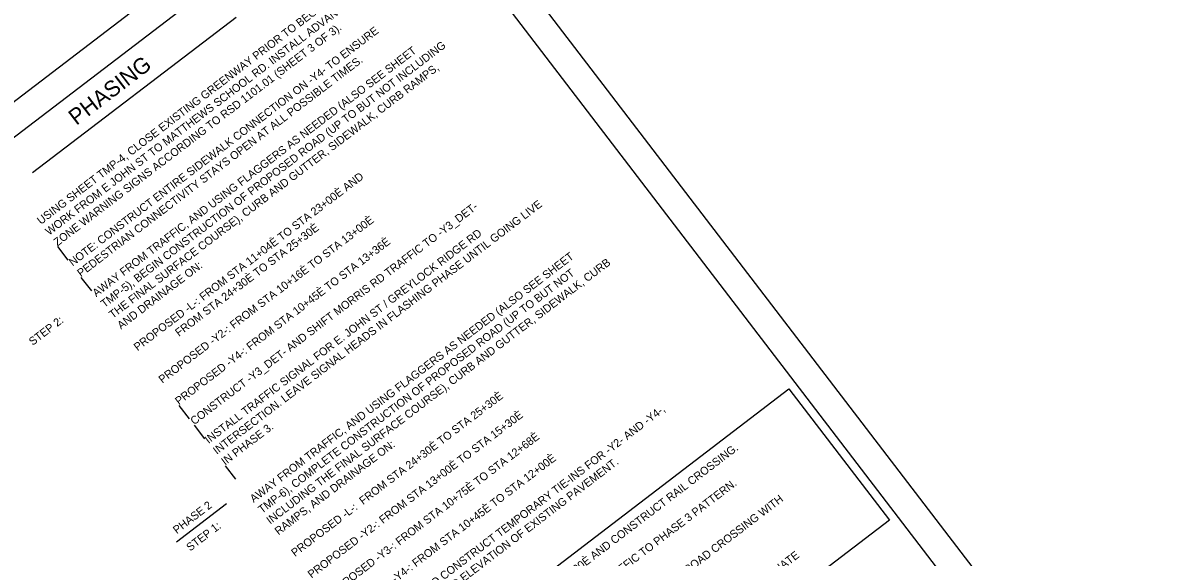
# Model space of a CAD drawing. Extents: x -606 to 2396, y -305 to 3662.
# Drawn here: x 1012 to 2005, y 1297 to 1764 of the extents above; entities that cross this region are included whole.
import ezdxf

# ---------------------------------------------------------------- set-up
doc = ezdxf.new("R2010")
doc.units = 0
for name, color, linetype in [('DEV BORDER CELL', 7, 'Continuous'), ('DEV TRANSPORTATION OPERATIONS PLAN SHEET', 7, 'Continuous'), ('Scratch_Level_4', 7, 'Continuous'), ('Sheet Plot Border Outside CELL', 7, 'Continuous'), ('Text', 7, 'Continuous')]:
    doc.layers.add(name, color=color, linetype=linetype)

msp = doc.modelspace()

# ---------------------------------------------------------------- linework, layer by layer
at = {"layer": 'DEV BORDER CELL'}
for p, q in [((1323.52, 1908.29), (148.3, 1009.63)), ((1963.25, 1088.61), (1337.94, 1906.36)), ((1020.15, 1633.31), (1198.1, 1769.38))]:
    msp.add_line(p, q, dxfattribs=at)
at = {"layer": 'Scratch_Level_4'}
for p, q in [((1041.93, 1568.52), (1051.04, 1556.6)), ((1062.52, 1541.59), (1071.64, 1529.67)), ((1148.17, 1429.58), (1157.28, 1417.67)), ((1161.54, 1412.1), (1170.65, 1400.19)), ((1188.56, 1376.77), (1197.67, 1364.85))]:
    msp.add_line(p, q, dxfattribs=at)
at = {"layer": 'Sheet Plot Border Outside CELL'}
msp.add_lwpolyline([(663.64, 50.42), (2004.54, 1075.77), (1336.37, 1949.58), (-4.54, 924.23)], close=True, dxfattribs=at)
at = {"layer": 'Text'}
msp.add_line((1145.98, 1310.15), (1189.87, 1343.71), dxfattribs=at)
msp.add_lwpolyline([(1276.8, 1134.37), (1681.63, 1443.93), (1769.46, 1329.08), (1364.63, 1019.52)], close=True, dxfattribs=at)

# ---------------------------------------------------------------- texts
at = {"layer": 'DEV TRANSPORTATION OPERATIONS PLAN SHEET'}
msp.add_text('PHASING', height=14, rotation=37.40396, dxfattribs=at).set_placement((1058.49, 1674.15))
at = {"layer": 'Text'}
for s, p in [('USING SHEET TMP-4, CLOSE EXISTING GREENWAY PRIOR TO BEGINNING ANY ', (1027.48, 1587.42)), ('WORK FROM E JOHN ST TO MATTHEWS SCHOOL RD. INSTALL ADVANCE WORK ', (1034.7, 1577.97)), ('ZONE WARNING SIGNS ACCORDING TO RSD 1101.01 (SHEET 3 OF 3).', (1041.93, 1568.52)), ('NOTE: CONSTRUCT ENTIRE SIDEWALK CONNECTION ON -Y4- TO ENSURE ', (1055.3, 1551.04)), ('TMP-5), BEGIN CONSTRUCTION OF PROPOSED ROAD (UP TO BUT NOT INCLUDING ', (1083.12, 1514.66)), ('AWAY FROM TRAFFIC, AND USING FLAGGERS AS NEEDED (ALSO SEE SHEET ', (1075.89, 1524.11)), ('PEDESTRIAN CONNECTIVITY STAYS OPEN AT ALL POSSIBLE TIMES.', (1062.52, 1541.59)), ('THE FINAL SURFACE COURSE), CURB AND GUTTER, SIDEWALK, CURB RAMPS, ', (1090.35, 1505.21)), ('PROPOSED -L-: FROM STA 11+04È TO STA 23+00È AND ', (1112.03, 1476.85)), ('INTERSECTION. LEAVE SIGNAL HEADS IN FLASHING PHASE UNTIL GOING LIVE ', (1181.33, 1386.22)), ('CONSTRUCT -Y3_DET- AND SHIFT MORRIS RD TRAFFIC TO -Y3_DET-', (1161.54, 1412.1)), ('PROPOSED -Y2-: FROM STA 10+16È TO STA 13+00È', (1133.72, 1448.49)), ('              FROM STA 24+30È TO STA 25+30È', (1119.26, 1467.39)), ('INSTALL TRAFFIC SIGNAL FOR E. JOHN ST / GREYLOCK RIDGE RD ', (1174.1, 1395.67)), ('PROPOSED -Y4-: FROM STA 10+45È TO STA 13+36È', (1148.17, 1429.58)), ('AWAY FROM TRAFFIC, AND USING FLAGGERS AS NEEDED (ALSO SEE SHEET ', (1213.56, 1344.07)), ('AND DRAINAGE ON:', (1097.57, 1495.75)), ('TMP-6), COMPLETE CONSTRUCTION OF PROPOSED ROAD (UP TO BUT NOT ', (1220.79, 1334.62)), ('INCLUDING THE FINAL SURFACE COURSE), CURB AND GUTTER, SIDEWALK, CURB ', (1228.02, 1325.16)), ('STEP 2:', (1020.28, 1481.59)), ('PROPOSED -L-:  FROM STA 24+30È TO STA 25+30È', (1249.7, 1296.8)), ('PROPOSED -Y2-: FROM STA 13+00È TO STA 15+30È', (1264.16, 1277.9)), ('USE FLAGGERS TO CONSTRUCT TEMPORARY TIE-INS FOR -Y2- AND -Y4-, ', (1307.53, 1221.18)), ('IN PHASE 3.', (1188.56, 1376.77)), ('PROPOSED -Y3-: FROM STA 10+75È TO STA 12+68È', (1278.62, 1258.99)), ('RAMPS, AND DRAINAGE ON:', (1235.25, 1315.71)), ('CLOSE -L- FROM STA 23+00È TO STA 24+30È AND CONSTRUCT RAIL CROSSING.', (1347.43, 1169)), ('PROPOSED -Y4-: FROM STA 10+45È TO STA 12+00È', (1293.07, 1240.08)), ('UP TO THE EDGE AND ELEVATION OF EXISTING PAVEMENT.', (1314.76, 1211.73)), ('PLACE TEMPORARY MARKINGS AND SHIFT TRAFFIC TO PHASE 3 PATTERN.', (1361.89, 1150.09)), ('CONTRACTOR TO COORDINATE CONSTRUCTION OF RAILROAD CROSSING WITH ', (1383.58, 1121.73)), ('PHASE 2', (1146.31, 1316.77)), ('STEP 1:', (1157.96, 1301.55)), ('CONSECUTIVE CALENDAR DAYS.  SEE SPECIFICATIONS FOR INTERMEDIATE ', (1412.49, 1083.92))]:
    msp.add_text(s, height=7, rotation=37.40396, dxfattribs=at).set_placement(p)

doc.saveas('drawing.dxf')
